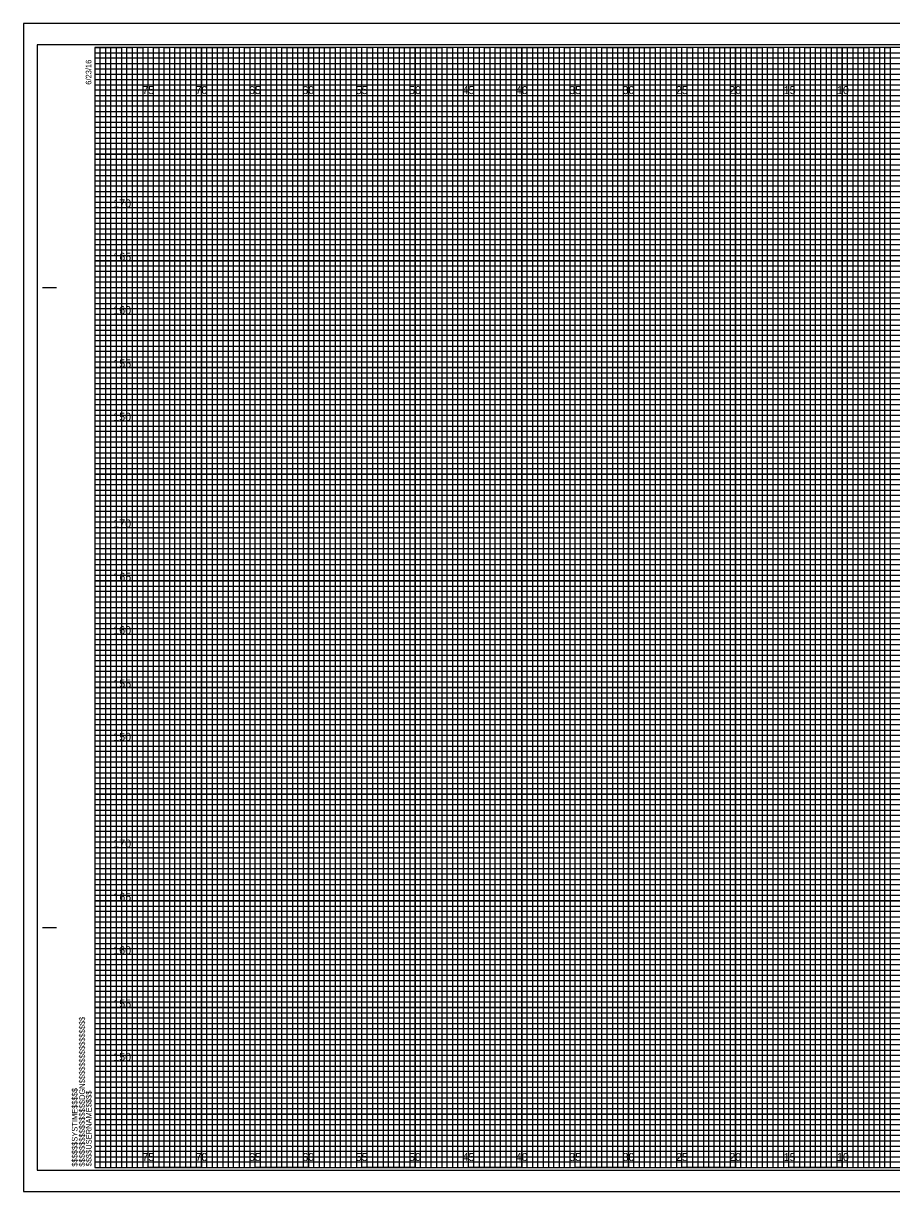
# Model space of a CAD drawing. Extents: x -7 to 162, y -2 to 107.
# Drawn here: x -6.7 to 74.6, y -2.3 to 107.3 of the extents above; entities that cross this region are included whole.
import ezdxf

# ---------------------------------------------------------------- set-up
doc = ezdxf.new("R2010")
doc.units = 0
for name, color, linetype in [('Prop XS Elevation Labels', 7, 'Continuous'), ('Prop XS Label Text', 7, 'Continuous'), ('Sheet Cross Section CELL', 7, 'Continuous'), ('Sheet Cross Section Grid Major CELL', 7, 'Continuous'), ('Sheet Cross Section Grid Middle CELL', 7, 'Continuous'), ('Sheet Cross Section Grid Minor 1 CELL', 7, 'Continuous'), ('Sheet Cross Section Grid Minor 2 CELL', 7, 'Continuous'), ('Sheet Cutting Line CELL', 7, 'Continuous'), ('Sheet DOT Grid CELL', 7, 'Continuous'), ('Sheet Plot Border Inside CELL', 7, 'Continuous'), ('Sheet Plot Border Outside CELL', 7, 'Continuous')]:
    doc.layers.add(name, color=color, linetype=linetype)

msp = doc.modelspace()

# ---------------------------------------------------------------- linework, layer by layer
at = {"layer": 'Sheet Cross Section CELL'}
for p, q in [((-4.9, 82.5), (-3.65, 82.5)), ((-4.85, 82.5), (-3.6, 82.5)), ((-4.9, 22.5), (-3.65, 22.5)), ((-4.85, 22.5), (-3.6, 22.5)), ((0, 0), (0, 0)), ((0, 0), (0, 0)), ((0, 0), (0, 0)), ((0, 0), (0, 0)), ((0, 0), (0, 0)), ((0, 0), (0, 0)), ((0, 0), (0, 0))]:
    msp.add_line(p, q, dxfattribs=at)
msp.add_lwpolyline([(160, 105), (0, 105), (0, 0), (160, 0)], close=True, dxfattribs=at)
at = {"layer": 'Sheet Cross Section Grid Major CELL'}
for p, q in [((5, 105), (0, 105)), ((5, 0), (5, 105)), ((15, 105), (10, 105)), ((10, 105), (10, 0)), ((15, 0), (15, 105)), ((25, 105), (20, 105)), ((20, 105), (20, 0)), ((25, 0), (25, 105)), ((35, 105), (30, 105)), ((30, 105), (30, 0)), ((35, 0), (35, 105)), ((45, 105), (40, 105)), ((40, 105), (40, 0)), ((45, 0), (45, 105)), ((55, 105), (50, 105)), ((50, 105), (50, 0)), ((55, 0), (55, 105)), ((65, 105), (60, 105)), ((60, 105), (60, 0)), ((65, 0), (65, 105)), ((75, 105), (70, 105)), ((70, 105), (70, 0)), ((10, 0), (5, 0)), ((20, 0), (15, 0)), ((30, 0), (25, 0)), ((40, 0), (35, 0)), ((50, 0), (45, 0)), ((60, 0), (55, 0)), ((70, 0), (65, 0))]:
    msp.add_line(p, q, dxfattribs=at)
for points in [[(0, 100), (160, 100), (160, 95), (0, 95)], [(0, 90), (160, 90), (160, 85), (0, 85)], [(0, 80), (160, 80), (160, 75), (0, 75)], [(0, 70), (160, 70), (160, 65), (0, 65)], [(0, 60), (160, 60), (160, 55), (0, 55)], [(0, 50), (160, 50), (160, 45), (0, 45)], [(0, 40), (160, 40), (160, 35), (0, 35)], [(0, 30), (160, 30), (160, 25), (0, 25)], [(0, 20), (160, 20), (160, 15), (0, 15)], [(0, 10), (160, 10), (160, 5), (0, 5)]]:
    msp.add_lwpolyline(points, dxfattribs=at)
at = {"layer": 'Sheet Cross Section Grid Middle CELL'}
for points in [[(0, 105), (2.5, 105), (2.5, 0), (7.5, 0), (7.5, 105), (12.5, 105), (12.5, 0), (17.5, 0), (17.5, 105), (22.5, 105), (22.5, 0), (27.5, 0), (27.5, 105), (32.5, 105), (32.5, 0), (37.5, 0), (37.5, 105), (42.5, 105), (42.5, 0), (47.5, 0), (47.5, 105), (52.5, 105), (52.5, 0), (57.5, 0), (57.5, 105), (62.5, 105), (62.5, 0), (67.5, 0), (67.5, 105), (72.5, 105), (72.5, 0), (77.5, 0)], [(0, 102.5), (137.5, 102.5)], [(0, 92.5), (160, 92.5), (160, 97.5), (0, 97.5)], [(0, 82.5), (160, 82.5), (160, 87.5), (0, 87.5)], [(0, 72.5), (160, 72.5), (160, 77.5), (0, 77.5)], [(0, 62.5), (160, 62.5), (160, 67.5), (0, 67.5)], [(0, 52.5), (160, 52.5), (160, 57.5), (0, 57.5)], [(0, 42.5), (160, 42.5), (160, 47.5), (0, 47.5)], [(0, 32.5), (160, 32.5), (160, 37.5), (0, 37.5)], [(0, 22.5), (160, 22.5), (160, 27.5), (0, 27.5)], [(0, 12.5), (160, 12.5), (160, 17.5), (0, 17.5)], [(0, 2.5), (160, 2.5), (160, 7.5), (0, 7.5)]]:
    msp.add_lwpolyline(points, dxfattribs=at)
at = {"layer": 'Sheet Cross Section Grid Minor 1 CELL'}
for p, q in [((0, 104.5), (130, 104.5)), ((130, 103.99), (0, 103.99)), ((0, 103.99), (0, 103.5)), ((0, 103.5), (130, 103.5)), ((130, 102.95), (0, 102.95)), ((0, 102.95), (0, 102)), ((0, 102), (160, 102))]:
    msp.add_line(p, q, dxfattribs=at)
for points in [[(0, 101.5), (135, 101.5), (160, 101.5), (160, 101), (0, 101)], [(0, 100.5), (160, 100.5), (160, 99.5), (0, 99.5)], [(0, 99), (160, 99), (160, 98.5), (0, 98.49)], [(0, 98), (160, 98), (160, 97), (0, 97)], [(0, 96.5), (160, 96.5), (160, 96), (0, 96)], [(0, 95.5), (160, 95.5), (160, 94.5), (0, 94.5)], [(0, 94), (160, 94), (160, 93.5), (0, 93.5)], [(0, 93), (160, 93), (160, 92), (0, 92)], [(0, 91.5), (160, 91.5), (160, 91), (0, 91)], [(0, 90.5), (160, 90.5), (160, 89.5), (0, 89.5)], [(0, 89), (160, 89), (160, 88.5), (0, 88.5)], [(0, 88), (160, 88), (160, 86.98), (160, 86.5), (160, 86), (0, 86)], [(0, 87), (160, 87), (160, 86.5), (0, 86.5)], [(0, 85.5), (160, 85.5), (160, 84.5), (0, 84.52)], [(0, 84.52), (160, 84.5), (160, 84), (0, 84)], [(0, 83.5), (160, 83.5), (160, 83), (0, 83)], [(0, 82), (160, 82), (160, 81.5), (0, 81.5)], [(0, 81), (160, 81), (160, 80.5), (0, 80.5)], [(-0.04, 79.45), (160, 79.45), (160, 78.94), (-0.04, 78.94)], [(0, 78.5), (160, 78.5), (160, 78), (0, 78)], [(0, 77), (160, 77), (160, 76.5), (0, 76.5)], [(0, 76), (160, 76), (160, 75.5), (0, 75.5)], [(0, 74.5), (160, 74.5), (160, 74), (0, 74)], [(0, 73.5), (160, 73.5), (160, 73), (0, 73)], [(0, 72), (160, 72), (160, 71.5), (0, 71.5)], [(0, 71), (160, 71), (160, 70.5), (0, 70.5)], [(0, 69.5), (160, 69.5), (160, 68.99), (0, 69)], [(0, 68.5), (160, 68.5), (160, 68), (0, 68)], [(0, 67), (160, 67), (160, 66.5), (0, 66.5)], [(0, 66), (160, 66), (160, 65.5), (0, 65.5)], [(0, 64.5), (160, 64.5), (160, 64), (0, 64)], [(0, 63.5), (160, 63.5), (160, 63), (0, 63)], [(0, 62), (160, 62), (160, 61.5), (0, 61.5)], [(0, 61), (160, 61), (160, 60.5), (0, 60.5)], [(0, 59.5), (160, 59.5), (160, 59), (0, 59)], [(0, 58.5), (160.03, 58.45), (160, 58), (0, 58)], [(0, 57), (160, 57), (160, 56.5), (0, 56.5)], [(0, 56), (160, 56), (160, 55.5), (0, 55.5)], [(0, 54.5), (160, 54.5), (160, 54), (0, 54)], [(0, 53.5), (160, 53.5), (160, 53), (0, 53)], [(0, 52), (160, 52), (160, 51.5), (0, 51.5)], [(0, 51), (160, 51), (160, 50.5), (0, 50.5)], [(0, 49.5), (160, 49.5), (160, 49), (0, 49)], [(0, 48.5), (160, 48.5), (160, 48), (0, 48)], [(0, 47), (160, 47), (160, 46.5), (0, 46.5)], [(0, 46), (160, 46), (160, 45.5), (0, 45.5)], [(0, 44.5), (160, 44.5), (160, 44), (0, 44)], [(0, 43.5), (160, 43.5), (160, 43), (0, 43)], [(0, 42), (160, 42), (160, 41.5), (0, 41.5)], [(0, 41), (160, 41), (160, 40.5), (0, 40.5)], [(0, 39.5), (160, 39.5), (160, 38.99), (0, 39)], [(0, 38.5), (160, 38.5), (160, 38), (0, 38)], [(0, 37), (160, 37), (160, 36.5), (0, 36.5)], [(0, 36), (160, 36), (160, 35.5), (0, 35.5)], [(0, 34.5), (160, 34.5), (160, 34), (0, 34)], [(0, 33.5), (160, 33.5), (160, 33), (0, 33)], [(0, 32), (160, 32), (160, 31.5), (0, 31.5)], [(0, 31), (160, 31), (160, 30.5), (0, 30.5)], [(0, 29.5), (160, 29.5), (160, 29), (0, 29)], [(0, 28.5), (160.03, 28.46), (160, 28), (0, 28)], [(0, 27), (160, 27), (160, 26.5), (0, 26.5)], [(0, 26), (160, 26), (160, 25.5), (0, 25.5)], [(0, 24.5), (160, 24.5), (160, 24), (0, 24)], [(0, 23.5), (160, 23.5), (160, 23), (0, 23)], [(0, 22), (160, 22), (160, 21.5), (0, 21.5)], [(0, 21), (160, 21), (160, 20.5), (0, 20.5)], [(0, 19.5), (160, 19.5), (160, 19), (0, 19)], [(0, 18.5), (160, 18.5), (160, 18), (0, 18)], [(0, 17), (160, 17), (160, 16.5), (0, 16.5)], [(0, 16), (160, 16), (160, 15.5), (0, 15.5)], [(0, 14.5), (160, 14.5), (160, 14), (0, 14)], [(0, 13.5), (160, 13.5), (160, 13), (0, 13)], [(0, 12), (160, 12), (160, 11.5), (0, 11.5)], [(0, 11), (160, 11), (160, 10.5), (0, 10.5)], [(0, 9.5), (160, 9.5), (160, 9), (0, 9)], [(0, 8.5), (160, 8.5), (160, 8), (0, 8)], [(0, 7), (160, 7), (160, 6.5), (0, 6.5)], [(0, 6), (160, 6), (160, 5.5), (0, 5.5)], [(0, 4.5), (160, 4.5), (160, 4), (0, 4)], [(0, 3.5), (160, 3.5), (160, 3), (0, 3)], [(0, 2), (160, 2), (160, 1.5), (0, 1.5)], [(0, 1), (160, 1), (160, 0.5), (0, 0.5)]]:
    msp.add_lwpolyline(points, dxfattribs=at)
at = {"layer": 'Sheet Cross Section Grid Minor 2 CELL'}
for points in [[(0, 0), (0.5, 0), (0.5, 105), (1, 105), (1, 0)], [(1, 0), (1.5, 0), (1.5, 105), (2, 105), (2, 0)], [(2.5, 0), (3, 0), (3, 105), (3.5, 105), (3.5, 0)], [(3.5, 0), (4, 0), (4, 105), (4.5, 105), (4.5, 0)], [(5, 0), (5.5, 0), (5.5, 105), (6, 105), (6, 0)], [(6, 0), (6.5, 0), (6.5, 105), (7, 105), (7, 0)], [(7.5, 0), (8, 0), (8, 105), (8.5, 105), (8.5, 0)], [(8.5, 0), (9, 0), (9, 105), (9.5, 105), (9.5, 0)], [(10, 0), (10.5, 0), (10.5, 105), (11, 105), (11, 0)], [(11, 0), (11.5, 0), (11.5, 105), (12, 105), (12, 0)], [(12.5, 0), (13, 0), (13, 105), (13.5, 105), (13.5, 0)], [(13.5, 0), (14, 0), (14, 105), (14.5, 105), (14.5, 0)], [(15, 0), (15.5, 0), (15.5, 105), (16, 105), (16, 0)], [(16, 0), (16.5, 0), (16.5, 105), (17, 105), (17, 0)], [(17.5, 0), (18, 0), (18, 105), (18.5, 105), (18.5, 0)], [(18.5, 0), (19, 0), (19, 105), (19.5, 105), (19.5, 0)], [(20, 0), (20.5, 0), (20.5, 105), (21, 105), (21, 0)], [(21, 0), (21.5, 0), (21.5, 105), (22, 105), (22, 0)], [(22.5, 0), (23, 0), (23, 105), (23.5, 105), (23.5, 0)], [(23.5, 0), (24, 0), (24, 105), (24.5, 105), (24.5, 0)], [(25, 0), (25.5, 0), (25.5, 105), (26, 105), (26, 0)], [(26, 0), (26.5, 0), (26.5, 105), (27, 105), (27, 0)], [(27.5, 0), (28, 0), (28, 105), (28.5, 105), (28.5, 0)], [(28.5, 0), (29, 0), (29, 105), (29.5, 105), (29.5, 0)], [(30, 0), (30.5, 0), (30.5, 105), (31, 105), (31, 0)], [(31, 0), (31.5, 0), (31.5, 105), (32, 105), (32, 0)], [(32.5, 0), (33, 0), (33, 105), (33.5, 105), (33.5, 0)], [(33.5, 0), (34, 0), (34, 105), (34.5, 105), (34.5, 0)], [(35, 0), (35.5, 0), (35.5, 105), (36, 105), (36, 0)], [(36, 0), (36.5, 0), (36.5, 105), (37, 105), (37, 0)], [(37.5, 0), (38, 0), (38, 105), (38.5, 105), (38.5, 0)], [(38.5, 0), (39, 0), (39, 105), (39.5, 105), (39.5, 0)], [(40, 0), (40.5, 0), (40.5, 105), (41, 105), (41, 0)], [(41, 0), (41.5, 0), (41.5, 105), (42, 105), (42, 0)], [(42.5, 0), (43, 0), (43, 105), (43.5, 105), (43.5, 0)], [(43.5, 0), (44, 0), (44, 105), (44.5, 105), (44.5, 0)], [(45, 0), (45.5, 0), (45.5, 105), (46, 105), (46, 0)], [(46, 0), (46.5, 0), (46.5, 105), (47, 105), (47, 0)], [(47.5, 0), (48, 0), (48, 105), (48.5, 105), (48.5, 0)], [(48.5, 0), (49, 0), (49, 105), (49.5, 105), (49.5, 0)], [(50, 0), (50.5, 0), (50.5, 105), (51, 105), (51, 0)], [(51, 0), (51.5, 0), (51.5, 105), (52, 105), (52, 0)], [(52.5, 0), (53, 0), (53, 105), (53.5, 105), (53.5, 0)], [(53.5, 0), (54, 0), (54, 105), (54.5, 105), (54.5, 0)], [(55, 0), (55.5, 0), (55.5, 105), (56, 105), (56, 0)], [(56, 0), (56.5, 0), (56.5, 105), (57, 105), (57, 0)], [(57.5, 0), (58, 0), (58, 105), (58.5, 105), (58.5, 0)], [(58.5, 0), (59, 0), (59, 105), (59.5, 105), (59.5, 0)], [(60, 0), (60.5, 0), (60.5, 105), (61, 105), (61, 0)], [(61, 0), (61.5, 0), (61.5, 105), (62, 105), (62, 0)], [(62.5, 0), (63, 0), (63, 105), (63.5, 105), (63.5, 0)], [(63.5, 0), (64, 0), (64, 105), (64.5, 105), (64.5, 0)], [(65, 0), (65.5, 0), (65.5, 105), (66, 105), (66, 0)], [(66, 0), (66.5, 0), (66.5, 105), (67, 105), (67, 0)], [(67.5, 0), (68, 0), (68, 105), (68.5, 105), (68.5, 0)], [(68.5, 0), (69, 0), (69, 105), (69.5, 105), (69.5, 0)], [(70, 0), (70.5, 0), (70.5, 105), (71, 105), (71, 0)], [(71, 0), (71.5, 0), (71.5, 105), (72, 105), (72, 0)], [(72.5, 0), (73, 0), (73, 105), (73.5, 105), (73.5, 0)], [(73.5, 0), (74, 0), (74, 105), (74.5, 105), (74.5, 0)]]:
    msp.add_lwpolyline(points, dxfattribs=at)
at = {"layer": 'Sheet Cutting Line CELL'}
for p, q in [((161.65, 107.25), (-6.7, 107.25)), ((-6.7, 107.25), (-6.7, -2.25)), ((-6.7, -2.25), (161.65, -2.25))]:
    msp.add_line(p, q, dxfattribs=at)
at = {"layer": 'Sheet DOT Grid CELL'}
for p, q in [((5, 0), (5, 105)), ((10, 0), (10, 105)), ((15, 0), (15, 105)), ((20, 0), (20, 105)), ((25, 0), (25, 105)), ((30, 0), (30, 105)), ((35, 0), (35, 105)), ((40, 0), (40, 105)), ((45, 0), (45, 105)), ((50, 0), (50, 105)), ((55, 0), (55, 105)), ((60, 0), (60, 105)), ((65, 0), (65, 105)), ((70, 0), (70, 105)), ((0, 100), (160, 100)), ((0, 95), (160, 95)), ((0, 90), (160, 90)), ((0, 85), (160, 85)), ((0, 80), (160, 80)), ((0, 75), (160, 75)), ((0, 70), (160, 70)), ((0, 65), (160, 65)), ((0, 60), (160, 60)), ((0, 55), (160, 55)), ((0, 50), (160, 50)), ((0, 45), (160, 45)), ((0, 40), (160, 40)), ((0, 35), (160, 35)), ((0, 30), (160, 30)), ((0, 25), (160, 25)), ((0, 20), (160, 20)), ((0, 15), (160, 15)), ((0, 10), (160, 10)), ((0, 5), (160, 5))]:
    msp.add_line(p, q, dxfattribs=at)
at = {"layer": 'Sheet Plot Border Inside CELL'}
msp.add_lwpolyline([(-5.4, -0.25), (161.2, -0.25), (161.2, 105.25), (-5.4, 105.25)], close=True, dxfattribs=at)
at = {"layer": 'Sheet Plot Border Outside CELL'}
msp.add_lwpolyline([(-6.7, -2.25), (161.65, -2.25), (161.65, 107.25), (-6.7, 107.25)], close=True, dxfattribs=at)

# ---------------------------------------------------------------- texts
at = {"layer": 'Prop XS Elevation Labels'}
for s, p in [('170', (1.72, 90)), ('165', (1.73, 85)), ('160', (1.72, 80)), ('155', (1.73, 75)), ('150', (1.72, 70)), ('170', (1.72, 60)), ('165', (1.73, 55)), ('160', (1.72, 50)), ('155', (1.73, 45)), ('150', (1.72, 40)), ('170', (1.72, 30)), ('165', (1.73, 25)), ('160', (1.72, 20)), ('155', (1.73, 15)), ('150', (1.72, 10))]:
    msp.add_text(s, height=0.75, dxfattribs=at).set_placement(p)
at = {"layer": 'Prop XS Label Text'}
for s, p in [('75', (4.44, 100.62)), ('70', (9.43, 100.62)), ('65', (14.44, 100.62)), ('60', (19.43, 100.62)), ('55', (24.44, 100.62)), ('50', (29.43, 100.62)), ('45', (34.44, 100.62)), ('40', (39.43, 100.62)), ('35', (44.44, 100.62)), ('30', (49.43, 100.62)), ('25', (54.44, 100.62)), ('20', (59.43, 100.62)), ('15', (64.53, 100.62)), ('10', (69.52, 100.62)), ('75', (4.44, 0.62)), ('70', (9.43, 0.62)), ('65', (14.44, 0.62)), ('60', (19.43, 0.62)), ('55', (24.44, 0.62)), ('50', (29.43, 0.62)), ('45', (34.44, 0.62)), ('40', (39.43, 0.62)), ('35', (44.44, 0.62)), ('30', (49.43, 0.62)), ('25', (54.44, 0.62)), ('20', (59.43, 0.62)), ('15', (64.53, 0.62)), ('10', (69.52, 0.62))]:
    msp.add_text(s, height=0.75, dxfattribs=at).set_placement(p)
at = {"layer": 'Sheet Cross Section CELL'}
for s, p in [('6/23/16', (-0.33, 101.5)), ('$$$$$$$$$$$$$$$$DGN$$$$$$$$$$$$$$$$', (-0.94, 0.09)), ('$$$$$$SYSTIME$$$$$', (-1.63, 0.09)), ('$$$$USERNAME$$$$', (-0.31, 0.12))]:
    msp.add_text(s, height=0.525, rotation=90, dxfattribs=at).set_placement(p)

doc.saveas('drawing.dxf')
